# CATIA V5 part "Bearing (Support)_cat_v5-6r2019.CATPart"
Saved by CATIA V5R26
Part number: Bearing (Support)
Bounding box of the stored display mesh (mm): x -270 to 10, y -39.842 to 39.842, z -34.808 to 139.842
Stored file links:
  D:\_Deepak\CATIA\CATIA V5 2015 Parts Files\Tutorial Files\Tutorials\c16_catia_v5_6r2016_tut\CV joint\Bearing (Support)_cat_v5-6r2012.CATPart
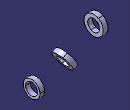
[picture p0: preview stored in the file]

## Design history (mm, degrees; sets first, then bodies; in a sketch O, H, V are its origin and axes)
Body1 (main body)
  Sketch1 on yz-plane, origin (0, 0, 0), H (0, 1, 0), V (0, 0, 1)
    circle A1 centre (0, 0) radius 25
    circle A2 centre (0, 0) radius 35
    radius A1 = 25
    radius A2 = 35
  Pad1: profile Sketch1, direction (1, 0, 0), length 10, mirrored extent
  Sketch2 on zx-plane, origin (0, 0, 0), H (-1, 0, 0), V (0, 0, 1)
    construction line L1 (0, 0) -> (60, 0)
    construction line L2 (60, 0) -> (194.1972, 77.4788)
    line L3 (107.5, 56.2917) -> (124.8205, 66.2917)
    line L4 (124.8205, 66.2917) -> (117.3205, 79.282)
    line L5 (117.3205, 79.282) -> (100, 69.282)
    point P6 (100, 69.282)
    line L6 (100, 69.282) -> (107.5, 56.2917)
    angle L2 L1 = 30
    distance L6 L4 = 20
    length L6 = 15
    distance L3 L2 = 25
    distance P6 V = 100
    length L1 = 60
    horizontal: L1 H
    perpendicularity: L4 L3
    parallelism: L5 L2, L6 L4
  Sketch3 on zx-plane, origin (0, 0, 0), H (-1, 0, 0), V (0, 0, 1)
    line L1 (60, 0) -> (221.9169, 93.4828)
    point P1 (60, 0)
    reference projected line E1 (107.5, 56.2917) -> (124.8205, 66.2917) from Sketch2.L3
    reference projected line E2 (107.5, 56.2917) -> (124.8205, 66.2917) from Sketch2.L3
    distance E2 L1 = 25
    coincidence: P1 H
    parallelism: L1 E1
  Shaft1: profile Sketch2, axis Sketch3.L1, angle 360
  Sketch4 on zx-plane, origin (0, 0, 0), H (-1, 0, 0), V (0, 0, 1)
    construction line L1 (188.3301, 100) -> (395.6544, 100)
    point P3 (260, 132.5)
    line L2 (270, 140) -> (270, 125)
    line L3 (270, 125) -> (250, 125)
    line L4 (250, 125) -> (250, 140)
    line L5 (250, 140) -> (270, 140)
    distance L1 H = 100
    length L5 = 20
    length L4 = 15
    distance L1 L3 = 25
    distance L4 V = 250
    horizontal: L1 H, L3 H, L5 H
    vertical: L2 V, L4 V
    equidistance: L2 L4 P3, L3 L5 P3
  Sketch5 on zx-plane, origin (0, 0, 0), H (-1, 0, 0), V (0, 0, 1)
    line L1 (210.3804, 100) -> (348.9415, 100)
    reference projected line E1 (250, 125) -> (270, 125) from Sketch4.L3
    distance L1 E1 = 25
    horizontal: L1 H
  Shaft2: profile Sketch4, axis Sketch5.L1, angle 360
